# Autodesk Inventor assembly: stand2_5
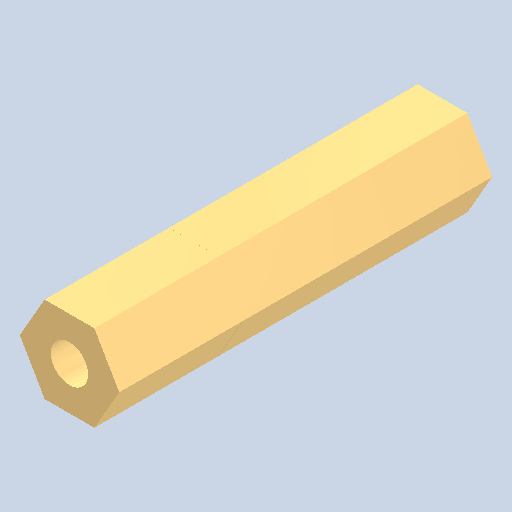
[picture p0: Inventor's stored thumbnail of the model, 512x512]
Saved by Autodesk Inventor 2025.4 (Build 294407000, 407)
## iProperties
Created: 2026-09
Part Number: stand2_5
Document SubType Name: Assembly
Designer: AdminForWorker
Title: stanofff v1
Author: AdminForWorker
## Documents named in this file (3)
- c:\worker\convert-fusion-r05-cosv3\tmp\job-1\19\temp\files\ca3d996b-dda0-445d-8bee-12a194174ca8\stanofff v1.iam
- c:\worker\convert-fusion-r05-cosv3\tmp\job-1\19\temp\files\ca3d996b-dda0-445d-8bee-12a194174ca8\M3-10 v1 (2).ipt
- c:\worker\convert-fusion-r05-cosv3\tmp\job-1\19\temp\files\ca3d996b-dda0-445d-8bee-12a194174ca8\M3-20 v1.ipt
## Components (2 placed, 2 different names)
1. M3-10 v1 (2):1
2. M3-20 v1:1
